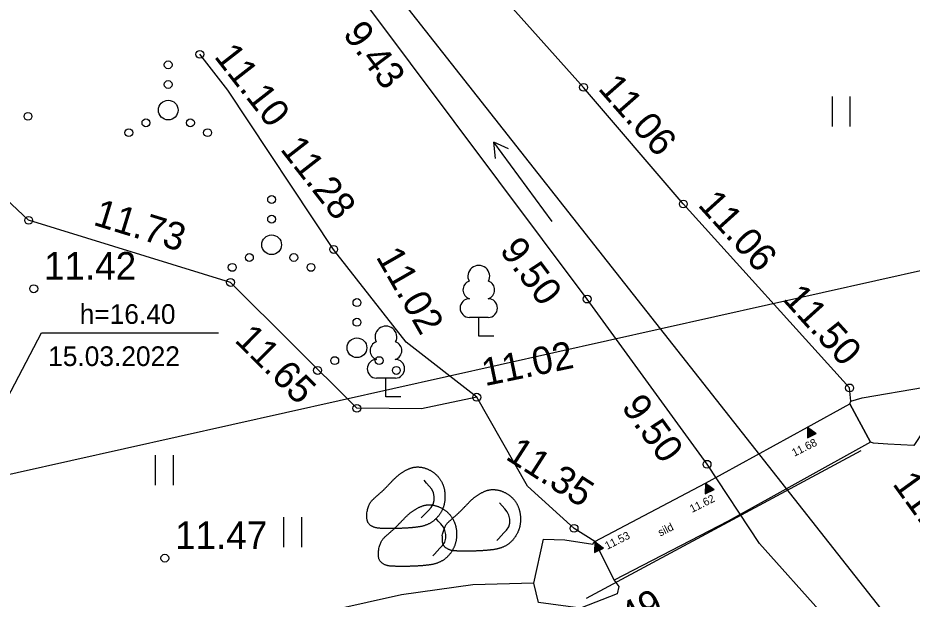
# Model space of a CAD drawing. Extents: x 554198 to 554371, y 6593448 to 6593563.
# Drawn here: x 554259.39 to 554282.11, y 6593502.46 to 6593517.24 of the extents above; entities that cross this region are included whole.
import ezdxf

# ---------------------------------------------------------------- set-up
doc = ezdxf.new("R2010")
doc.units = 0
for name, color, linetype in [('AED', 7, 'Continuous'), ('HALJASTUS', 7, 'Continuous'), ('KORGUS-EH2000', 7, 'Continuous'), ('MPOHULIIN', 7, 'Continuous'), ('PIIR', 7, 'Continuous'), ('PUU', 7, 'Continuous'), ('RAJATIS', 7, 'Continuous'), ('RAJATISEDET', 7, 'Continuous'), ('RELJEEF', 7, 'Continuous'), ('TEE', 7, 'Continuous'), ('VEEKOGU', 7, 'Continuous')]:
    doc.layers.add(name, color=color, linetype=linetype)

msp = doc.modelspace()

# ---------------------------------------------------------------- linework, layer by layer
at = {"layer": 'AED'}
msp.add_lwpolyline([(554280.802, 6593506.228), (554273.828, 6593502.478)], dxfattribs=at)
at = {"layer": 'HALJASTUS'}
for p, q in [((554280.072, 6593515.238), (554280.072, 6593514.476)), ((554280.528, 6593515.238), (554280.528, 6593514.476)), ((554262.878, 6593506.117), (554262.878, 6593505.355)), ((554263.333, 6593506.117), (554263.333, 6593505.355)), ((554266.139, 6593504.541), (554266.139, 6593503.78)), ((554266.594, 6593504.541), (554266.594, 6593503.78))]:
    msp.add_line(p, q, dxfattribs=at)
msp.add_lwpolyline([(554271.046, 6593507.591), (554269.64, 6593507.3), (554268, 6593507.31), (554264.79, 6593510.51), (554259.66, 6593512.09), (554255.53, 6593515.97)], dxfattribs=at)
for centre, radius in [((554263.206, 6593516.042), 0.1), ((554263.206, 6593515.542), 0.1), ((554263.206, 6593514.892), 0.25), ((554259.643, 6593514.733), 0.1), ((554262.641, 6593514.567), 0.1), ((554263.771, 6593514.567), 0.1), ((554262.206, 6593514.317), 0.1), ((554264.206, 6593514.317), 0.1), ((554265.834, 6593512.618), 0.1), ((554265.834, 6593512.118), 0.1), ((554265.834, 6593511.468), 0.25), ((554265.269, 6593511.143), 0.1), ((554266.399, 6593511.143), 0.1), ((554264.834, 6593510.893), 0.1), ((554266.834, 6593510.893), 0.1), ((554268.002, 6593509.998), 0.1), ((554268.002, 6593509.498), 0.1), ((554268.002, 6593508.848), 0.25), ((554267.437, 6593508.523), 0.1), ((554268.567, 6593508.523), 0.1), ((554267.002, 6593508.273), 0.1), ((554269.002, 6593508.273), 0.1)]:
    msp.add_circle(centre, radius, dxfattribs=at)
at = {"layer": 'KORGUS-EH2000'}
for centre in [(554264.01, 6593516.31), (554273.76, 6593515.47), (554276.294, 6593512.505), (554259.66, 6593512.09), (554267.41, 6593511.35), (554264.79, 6593510.51), (554259.79, 6593510.35), (554273.851, 6593510.088), (554280.518, 6593507.828), (554271.046, 6593507.591), (554268, 6593507.31), (554276.897, 6593505.887), (554273.518, 6593504.258), (554263.12, 6593503.5)]:
    msp.add_circle(centre, 0.1, dxfattribs=at)
at = {"layer": 'MPOHULIIN'}
for points in [[(554282.548, 6593510.856), (554248.452, 6593503.231)], [(554257.956, 6593505.356), (554259.983, 6593509.225), (554264.482, 6593509.225)]]:
    msp.add_lwpolyline(points, dxfattribs=at)
at = {"layer": 'PIIR'}
msp.add_line((554294.582, 6593485.373), (554263.353, 6593525.033), dxfattribs=at)
at = {"layer": 'PUU'}
for p, q in [((554271.338, 6593509.621), (554270.858, 6593509.621)), ((554271.098, 6593509.146), (554271.098, 6593509.621)), ((554271.478, 6593509.146), (554271.098, 6593509.146)), ((554268.979, 6593508.079), (554268.499, 6593508.079)), ((554268.739, 6593507.604), (554268.739, 6593508.079)), ((554269.119, 6593507.604), (554268.739, 6593507.604))]:
    msp.add_line(p, q, dxfattribs=at)
for centre, radius, start, end in [((554271.098, 6593510.666), 0.277, 332.5799, 207.4201), ((554270.928, 6593510.319), 0.233, 109.0217, 253.1415), ((554271.268, 6593510.319), 0.233, 286.8508, 70.9859), ((554270.861, 6593509.858), 0.238, 90.0016, 269.3953), ((554271.335, 6593509.858), 0.238, 270.6047, 89.9984), ((554268.739, 6593509.124), 0.277, 332.5799, 207.4201), ((554268.569, 6593508.777), 0.233, 109.0217, 253.1415), ((554268.909, 6593508.777), 0.233, 286.8508, 70.9859), ((554268.502, 6593508.316), 0.238, 90.0016, 269.3953), ((554268.976, 6593508.316), 0.238, 270.6047, 89.9984)]:
    msp.add_arc(centre, radius, start, end, dxfattribs=at)
at = {"layer": 'RAJATIS'}
msp.add_lwpolyline([(554276.856, 6593505.409), (554279.452, 6593506.835), (554280.525, 6593507.42), (554281.051, 6593506.447), (554277.436, 6593504.444), (554274.534, 6593502.939), (554274.044, 6593503.92)], close=True, dxfattribs=at)
at = {"layer": 'RAJATISEDET'}
for p, q in [((554279.452, 6593506.835), (554279.448, 6593506.562)), ((554279.448, 6593506.562), (554279.67, 6593506.67)), ((554279.564, 6593506.619), (554279.449, 6593506.642)), ((554279.662, 6593506.676), (554279.45, 6593506.718)), ((554279.657, 6593506.664), (554279.45, 6593506.705)), ((554279.639, 6593506.655), (554279.45, 6593506.693)), ((554279.62, 6593506.646), (554279.45, 6593506.68)), ((554279.602, 6593506.637), (554279.45, 6593506.667)), ((554279.583, 6593506.628), (554279.45, 6593506.655)), ((554279.525, 6593506.78), (554279.451, 6593506.794)), ((554279.548, 6593506.762), (554279.451, 6593506.782)), ((554279.571, 6593506.745), (554279.451, 6593506.769)), ((554279.594, 6593506.728), (554279.451, 6593506.756)), ((554279.616, 6593506.711), (554279.451, 6593506.744)), ((554279.639, 6593506.693), (554279.451, 6593506.731)), ((554279.452, 6593506.835), (554279.67, 6593506.67)), ((554279.456, 6593506.832), (554279.452, 6593506.832)), ((554279.479, 6593506.814), (554279.452, 6593506.82)), ((554279.502, 6593506.797), (554279.452, 6593506.807)), ((554279.472, 6593506.574), (554279.448, 6593506.578)), ((554279.453, 6593506.565), (554279.448, 6593506.566)), ((554279.546, 6593506.61), (554279.449, 6593506.629)), ((554279.527, 6593506.601), (554279.449, 6593506.616)), ((554279.509, 6593506.592), (554279.449, 6593506.604)), ((554279.49, 6593506.583), (554279.449, 6593506.591)), ((554276.856, 6593505.409), (554276.852, 6593505.136)), ((554277.066, 6593505.25), (554276.854, 6593505.292)), ((554277.061, 6593505.238), (554276.854, 6593505.279)), ((554276.929, 6593505.354), (554276.855, 6593505.368)), ((554276.952, 6593505.336), (554276.855, 6593505.356)), ((554276.975, 6593505.319), (554276.855, 6593505.343)), ((554276.998, 6593505.302), (554276.855, 6593505.33)), ((554277.02, 6593505.285), (554276.855, 6593505.318)), ((554277.043, 6593505.267), (554276.855, 6593505.305)), ((554276.856, 6593505.409), (554277.074, 6593505.244)), ((554276.86, 6593505.406), (554276.856, 6593505.406)), ((554276.883, 6593505.388), (554276.856, 6593505.394)), ((554276.906, 6593505.371), (554276.856, 6593505.381)), ((554276.852, 6593505.136), (554277.074, 6593505.244)), ((554276.876, 6593505.148), (554276.852, 6593505.152)), ((554276.857, 6593505.139), (554276.852, 6593505.14)), ((554276.968, 6593505.193), (554276.853, 6593505.216)), ((554276.95, 6593505.184), (554276.853, 6593505.203)), ((554276.931, 6593505.175), (554276.853, 6593505.19)), ((554276.913, 6593505.166), (554276.853, 6593505.178)), ((554276.894, 6593505.157), (554276.853, 6593505.165)), ((554277.043, 6593505.229), (554276.854, 6593505.267)), ((554277.024, 6593505.22), (554276.854, 6593505.254)), ((554277.006, 6593505.211), (554276.854, 6593505.241)), ((554276.987, 6593505.202), (554276.854, 6593505.229)), ((554274.044, 6593503.92), (554274.04, 6593503.647)), ((554274.044, 6593503.92), (554274.262, 6593503.755)), ((554274.048, 6593503.917), (554274.044, 6593503.917)), ((554274.04, 6593503.647), (554274.262, 6593503.755)), ((554274.156, 6593503.704), (554274.041, 6593503.727)), ((554274.138, 6593503.695), (554274.041, 6593503.714)), ((554274.119, 6593503.686), (554274.041, 6593503.701)), ((554274.101, 6593503.677), (554274.041, 6593503.689)), ((554274.254, 6593503.761), (554274.042, 6593503.803)), ((554274.249, 6593503.749), (554274.042, 6593503.79)), ((554274.231, 6593503.74), (554274.042, 6593503.778)), ((554274.212, 6593503.731), (554274.042, 6593503.765)), ((554274.194, 6593503.722), (554274.042, 6593503.752)), ((554274.175, 6593503.713), (554274.042, 6593503.74)), ((554274.117, 6593503.865), (554274.043, 6593503.879)), ((554274.14, 6593503.847), (554274.043, 6593503.867)), ((554274.163, 6593503.83), (554274.043, 6593503.854)), ((554274.186, 6593503.813), (554274.043, 6593503.841)), ((554274.208, 6593503.796), (554274.043, 6593503.829)), ((554274.231, 6593503.778), (554274.043, 6593503.816)), ((554274.071, 6593503.899), (554274.044, 6593503.905)), ((554274.094, 6593503.882), (554274.044, 6593503.892)), ((554274.064, 6593503.659), (554274.04, 6593503.663)), ((554274.045, 6593503.65), (554274.04, 6593503.651)), ((554274.082, 6593503.668), (554274.041, 6593503.676))]:
    msp.add_line(p, q, dxfattribs=at)
at = {"layer": 'RELJEEF'}
for points in [[(554269.637, 6593504.524), (554269.68, 6593504.569), (554269.748, 6593504.642), (554269.816, 6593504.716), (554269.884, 6593504.789), (554269.94, 6593504.871), (554269.965, 6593504.968), (554269.965, 6593505.067), (554269.944, 6593505.165), (554269.902, 6593505.255), (554269.839, 6593505.333), (554269.773, 6593505.408), (554269.707, 6593505.483)], [(554271.556, 6593503.949), (554271.599, 6593503.994), (554271.667, 6593504.067), (554271.735, 6593504.141), (554271.803, 6593504.214), (554271.859, 6593504.296), (554271.884, 6593504.393), (554271.884, 6593504.492), (554271.863, 6593504.59), (554271.821, 6593504.68), (554271.758, 6593504.758), (554271.692, 6593504.833), (554271.626, 6593504.908)], [(554269.932, 6593503.561), (554269.975, 6593503.606), (554270.043, 6593503.679), (554270.111, 6593503.753), (554270.179, 6593503.826), (554270.235, 6593503.908), (554270.26, 6593504.005), (554270.26, 6593504.104), (554270.239, 6593504.202), (554270.197, 6593504.292), (554270.134, 6593504.37), (554270.068, 6593504.445), (554270.002, 6593504.52)]]:
    msp.add_lwpolyline(points, dxfattribs=at)
for points in [[(554268.252, 6593504.654), (554268.252, 6593504.654), (554268.257, 6593504.395), (554268.451, 6593504.266), (554268.7, 6593504.254), (554268.95, 6593504.253), (554269.2, 6593504.26), (554269.45, 6593504.278), (554269.697, 6593504.313), (554269.923, 6593504.416), (554270.098, 6593504.592), (554270.212, 6593504.814), (554270.247, 6593505.06), (554270.217, 6593505.308), (554270.11, 6593505.532), (554269.93, 6593505.704), (554269.704, 6593505.808), (554269.457, 6593505.827), (554269.226, 6593505.733), (554269.022, 6593505.589), (554268.848, 6593505.41), (554268.675, 6593505.229), (554268.487, 6593505.066), (554268.305, 6593504.897), (554268.252, 6593504.654)], [(554270.171, 6593504.079), (554270.171, 6593504.079), (554270.176, 6593503.82), (554270.37, 6593503.691), (554270.619, 6593503.679), (554270.869, 6593503.678), (554271.119, 6593503.685), (554271.369, 6593503.703), (554271.616, 6593503.738), (554271.842, 6593503.841), (554272.017, 6593504.017), (554272.131, 6593504.239), (554272.166, 6593504.485), (554272.136, 6593504.733), (554272.029, 6593504.957), (554271.849, 6593505.129), (554271.623, 6593505.233), (554271.376, 6593505.252), (554271.145, 6593505.158), (554270.941, 6593505.014), (554270.767, 6593504.835), (554270.594, 6593504.654), (554270.406, 6593504.491), (554270.224, 6593504.322), (554270.171, 6593504.079)], [(554268.547, 6593503.691), (554268.547, 6593503.691), (554268.552, 6593503.432), (554268.746, 6593503.303), (554268.995, 6593503.291), (554269.245, 6593503.29), (554269.495, 6593503.297), (554269.745, 6593503.315), (554269.992, 6593503.35), (554270.218, 6593503.453), (554270.393, 6593503.629), (554270.507, 6593503.851), (554270.542, 6593504.097), (554270.512, 6593504.345), (554270.405, 6593504.569), (554270.225, 6593504.741), (554269.999, 6593504.845), (554269.752, 6593504.864), (554269.521, 6593504.77), (554269.317, 6593504.626), (554269.143, 6593504.447), (554268.97, 6593504.266), (554268.782, 6593504.103), (554268.6, 6593503.934), (554268.547, 6593503.691)]]:
    msp.add_open_spline(points, degree=2, dxfattribs=at)
at = {"layer": 'TEE'}
for points in [[(554280.554, 6593507.491), (554280.84, 6593507.575), (554282.423, 6593507.849), (554282.4, 6593506.737), (554282.147, 6593506.366), (554281.493, 6593506.397), (554281.123, 6593506.423), (554281.051, 6593506.447), (554280.525, 6593507.42)], [(554274.579, 6593502.878), (554274.655, 6593502.782), (554274.616, 6593502.597), (554273.684, 6593502.229), (554272.617, 6593502.372), (554272.497, 6593502.867), (554272.745, 6593503.98), (554273.284, 6593503.965), (554273.992, 6593503.859), (554274.044, 6593503.92), (554274.534, 6593502.939)]]:
    msp.add_lwpolyline(points, close=True, dxfattribs=at)
msp.add_lwpolyline([(554272.497, 6593502.867), (554270.945, 6593502.819), (554269.137, 6593502.567), (554267.385, 6593502.182), (554264.175, 6593501.658), (554257.446, 6593501.567)], dxfattribs=at)
at = {"layer": 'VEEKOGU'}
for p in [(554272.963, 6593512.062), (554271.524, 6593513.662), (554271.856, 6593513.908)]:
    msp.add_line(p, (554271.477, 6593514.073), dxfattribs=at)
for points in [[(554280.554, 6593507.491), (554280.518, 6593507.828), (554276.294, 6593512.505), (554273.76, 6593515.47), (554269.8, 6593519.901)], [(554289.699, 6593489.692), (554285.677, 6593494.745), (554279.884, 6593502.023), (554278.226, 6593503.871), (554276.897, 6593505.887), (554273.851, 6593510.088), (554268.23, 6593517.601), (554267.552, 6593518.507)], [(554274.044, 6593503.92), (554273.518, 6593504.258), (554272.338, 6593505.333), (554271.046, 6593507.591), (554269.25, 6593508.99), (554267.41, 6593511.35), (554264.72, 6593515.4), (554264.01, 6593516.31)]]:
    msp.add_lwpolyline(points, dxfattribs=at)

# ---------------------------------------------------------------- texts
at = {"layer": 'KORGUS-EH2000'}
for s, rotation, p in [(' 9.43 ', 306.8091, (554267.469, 6593517.032)), (' 11.10 ', 307.9621, (554264.194, 6593516.454)), (' 11.06 ', 311.2845, (554273.935, 6593515.624)), (' 11.28 ', 307.9422, (554265.874, 6593514.097)), (' 11.06 ', 312.0866, (554276.467, 6593512.661)), (' 11.73 ', 342.8816, (554261.027, 6593512.057)), (' 9.50 ', 306.8027, (554271.452, 6593511.532)), (' 11.02 ', 299.7777, (554268.342, 6593511.388)), (' 11.50 ', 312.0866, (554278.616, 6593510.27)), (' 11.65 ', 315.0894, (554264.685, 6593509.205)), (' 11.02 ', 11.6934, (554270.999, 6593507.819)), (' 9.50 ', 305.9446, (554274.55, 6593507.552)), (' 11.35 ', 327.2758, (554271.53, 6593506.176)), (' 11.64 ', 305.8484, (554281.438, 6593505.597)), (' 11.49 ', 26.8242, (554273.515, 6593500.955))]:
    msp.add_text(s, height=0.7, rotation=rotation, dxfattribs=at).set_placement(p)
for s, p in [(' 11.42 ', (554259.79, 6593510.583)), (' 11.47 ', (554263.12, 6593503.733))]:
    msp.add_text(s, height=0.7, dxfattribs=at).set_placement(p)
at = {"layer": 'MPOHULIIN'}
for s, p in [('h=16.40', (554260.957, 6593509.457)), ('15.03.2022', (554260.156, 6593508.385))]:
    msp.add_text(s, height=0.5, dxfattribs=at).set_placement(p)
at = {"layer": 'RAJATIS'}
msp.add_text('sild', height=0.2, rotation=26.5951, dxfattribs=at).set_placement((554275.71, 6593504.048))
at = {"layer": 'RAJATISEDET'}
for s, p in [('11.68', (554279.114, 6593506.076)), ('11.62', (554276.518, 6593504.65)), ('11.53', (554274.361, 6593503.712))]:
    msp.add_text(s, height=0.2, rotation=26.5951, dxfattribs=at).set_placement(p)

doc.saveas('drawing.dxf')
